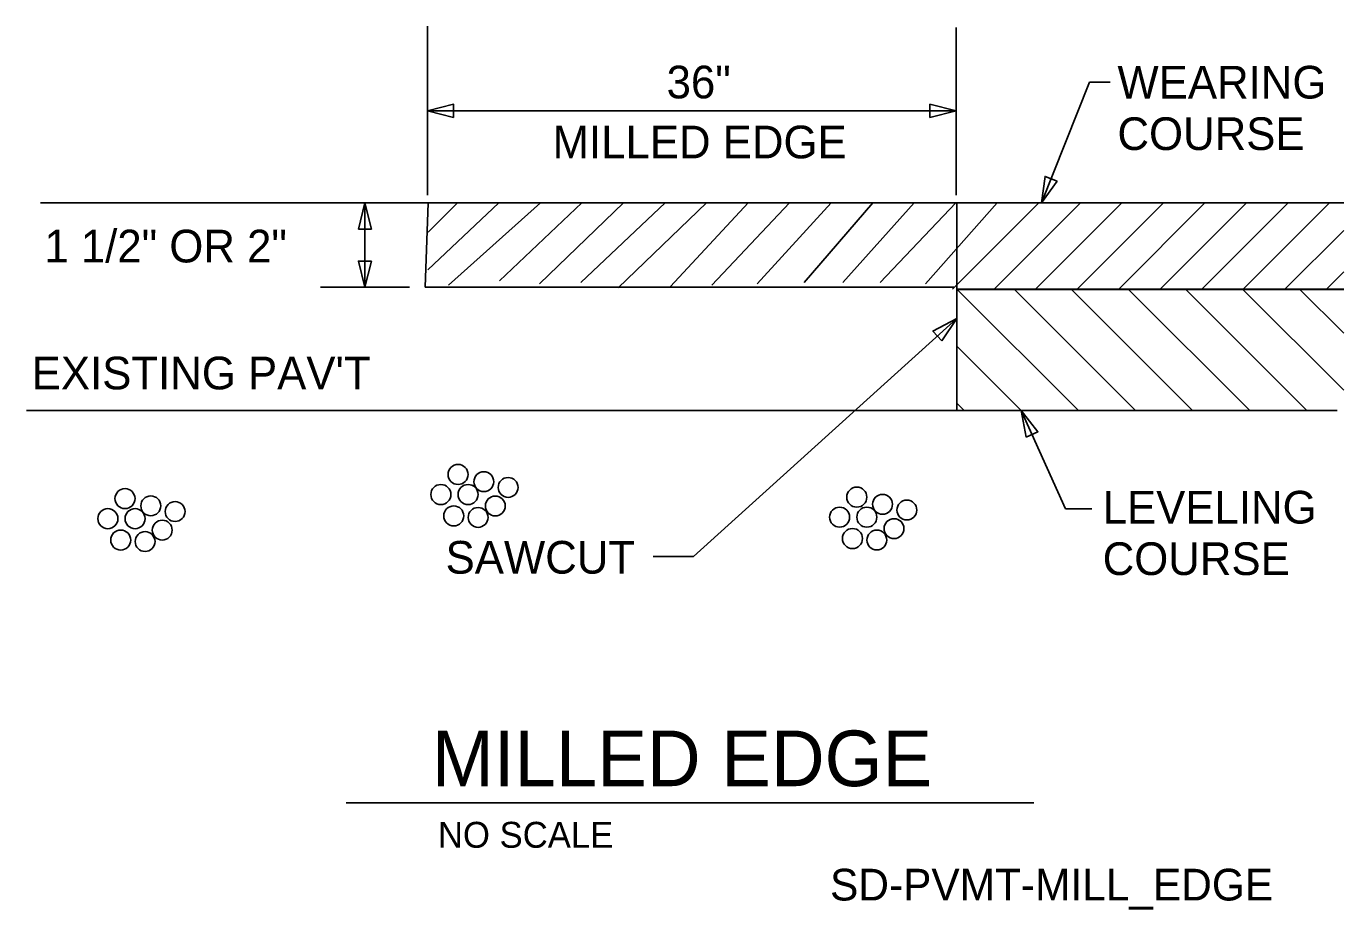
# Model space of a CAD drawing. Extents: x 10126.6 to 10168.6, y 10025.9 to 10054.1.
import ezdxf

# ---------------------------------------------------------------- set-up
doc = ezdxf.new("R2010")
doc.units = 0
for name, color, linetype in [('Default', 7, 'Continuous'), ('G-ANNO-TEXT', 7, 'Continuous'), ('G-ANNO-TTXT', 7, 'Continuous'), ('G-DETL-LINE', 7, 'Continuous'), ('G-DETL-PATT', 7, 'Continuous')]:
    doc.layers.add(name, color=color, linetype=linetype)

msp = doc.modelspace()

# ---------------------------------------------------------------- linework, layer by layer
at = {"layer": 'Default'}
for p, q in [((10139.407, 10048.484), (10139.319, 10045.8)), ((10156.278, 10045.72), (10168.633, 10045.72)), ((10156.28, 10045.73), (10156.28, 10041.854)), ((10156.52, 10041.854), (10156.28, 10042.094))]:
    msp.add_line(p, q, dxfattribs=at)
at = {"layer": 'G-ANNO-TEXT'}
for p, q in [((10139.389, 10048.73), (10139.389, 10054.126)), ((10156.26, 10048.73), (10156.26, 10054.085)), ((10160.523, 10052.343), (10161.184, 10052.343)), ((10139.389, 10051.428), (10156.26, 10051.428)), ((10137.392, 10045.795), (10137.392, 10048.484)), ((10156.28, 10048.484), (10156.28, 10045.73)), ((10138.812, 10045.795), (10135.973, 10045.795)), ((10136.796, 10029.328), (10158.746, 10029.328))]:
    msp.add_line(p, q, dxfattribs=at)
for points in [[(10140.222, 10051.219), (10139.389, 10051.428), (10140.222, 10051.636)], [(10155.427, 10051.636), (10156.26, 10051.428), (10155.427, 10051.219)], [(10137.184, 10047.651), (10137.392, 10048.484), (10137.601, 10047.651)], [(10137.601, 10046.629), (10137.392, 10045.795), (10137.184, 10046.629)], [(10155.802, 10044.084), (10156.28, 10044.798), (10155.522, 10044.393)]]:
    msp.add_lwpolyline(points, close=True, dxfattribs=at)
msp.add_lwpolyline([(10156.28, 10044.798), (10147.878, 10037.197), (10146.587, 10037.197)], dxfattribs=at)
at = {"layer": 'G-ANNO-TTXT'}
msp.add_line((10158.987, 10048.484), (10160.523, 10052.343), dxfattribs=at)
for points in [[(10159.489, 10049.181), (10158.987, 10048.484), (10159.102, 10049.335)], [(10159.489, 10049.181), (10158.987, 10048.484), (10159.102, 10049.335)], [(10158.496, 10041.008), (10158.343, 10041.854), (10158.876, 10041.18)]]:
    msp.add_lwpolyline(points, close=True, dxfattribs=at)
msp.add_lwpolyline([(10158.343, 10041.854), (10159.758, 10038.718), (10160.594, 10038.718)], dxfattribs=at)
at = {"layer": 'G-DETL-LINE'}
for p, q in [((10127.039, 10048.484), (10139.407, 10048.484)), ((10139.407, 10048.484), (10168.633, 10048.484)), ((10139.319, 10045.8), (10156.19, 10045.8)), ((10156.278, 10045.73), (10168.633, 10045.73)), ((10126.584, 10041.854), (10168.429, 10041.854))]:
    msp.add_line(p, q, dxfattribs=at)
at = {"layer": 'G-DETL-PATT'}
for p, q in [((10139.395, 10046.346), (10141.666, 10048.484)), ((10139.407, 10047.551), (10140.341, 10048.484)), ((10140.056, 10045.861), (10142.992, 10048.484)), ((10141.685, 10045.993), (10144.318, 10048.484)), ((10142.961, 10045.905), (10145.644, 10048.484)), ((10144.282, 10045.949), (10146.97, 10048.484)), ((10145.471, 10045.773), (10148.295, 10048.484)), ((10147.144, 10045.817), (10149.621, 10048.484)), ((10148.464, 10045.861), (10150.947, 10048.484)), ((10149.917, 10045.905), (10152.273, 10048.484)), ((10151.414, 10045.949), (10153.599, 10048.484)), ((10152.647, 10045.949), (10154.925, 10048.484)), ((10153.835, 10045.949), (10156.25, 10048.484)), ((10155.288, 10045.905), (10157.576, 10048.484)), ((10156.148, 10045.73), (10158.902, 10048.484)), ((10157.473, 10045.73), (10160.228, 10048.484)), ((10158.799, 10045.73), (10161.554, 10048.484)), ((10160.125, 10045.73), (10162.88, 10048.484)), ((10161.451, 10045.73), (10164.205, 10048.484)), ((10162.777, 10045.73), (10165.531, 10048.484)), ((10164.102, 10045.73), (10166.857, 10048.484)), ((10165.428, 10045.73), (10168.183, 10048.484)), ((10166.754, 10045.73), (10168.633, 10047.608)), ((10168.08, 10045.73), (10168.633, 10046.282)), ((10160.166, 10041.854), (10156.29, 10045.73)), ((10161.989, 10041.854), (10158.113, 10045.73)), ((10163.812, 10041.854), (10159.936, 10045.73)), ((10165.635, 10041.854), (10161.759, 10045.73)), ((10167.458, 10041.854), (10163.582, 10045.73)), ((10168.633, 10042.502), (10165.405, 10045.73)), ((10168.633, 10044.325), (10167.228, 10045.73)), ((10158.343, 10041.854), (10156.28, 10043.917))]:
    msp.add_line(p, q, dxfattribs=at)
for centre, radius in [((10140.364, 10039.814), 0.32), ((10141.187, 10039.584), 0.317), ((10141.962, 10039.401), 0.317), ((10129.733, 10039.043), 0.32), ((10139.816, 10039.173), 0.32), ((10140.684, 10039.173), 0.32), ((10153.091, 10039.091), 0.32), ((10153.914, 10038.861), 0.317), ((10130.556, 10038.813), 0.317), ((10131.332, 10038.63), 0.317), ((10140.226, 10038.491), 0.32), ((10141.004, 10038.443), 0.317), ((10141.552, 10038.808), 0.317), ((10152.544, 10038.451), 0.32), ((10153.412, 10038.451), 0.32), ((10154.69, 10038.678), 0.317), ((10129.186, 10038.403), 0.32), ((10130.054, 10038.403), 0.32), ((10130.922, 10038.037), 0.317), ((10154.28, 10038.085), 0.317), ((10129.596, 10037.72), 0.32), ((10130.374, 10037.672), 0.317), ((10152.954, 10037.768), 0.32), ((10153.732, 10037.72), 0.317)]:
    msp.add_circle(centre, radius, dxfattribs=at)

# ---------------------------------------------------------------- texts
at = {"layer": 'G-ANNO-TEXT'}
for s, height, p in [('36"', 1.044, (10147.021, 10051.825)), ('WEARING ', 1.044, (10161.412, 10051.82)), ('MILLED EDGE', 1.044, (10143.382, 10049.91)), ('COURSE', 1.044, (10161.412, 10050.176)), ("EXISTING PAV'T", 1.044, (10126.755, 10042.532)), ('LEVELING ', 1.044, (10160.94, 10038.247)), ('SAWCUT', 1.044, (10139.966, 10036.647)), ('COURSE', 1.044, (10160.94, 10036.603)), ('MILLED EDGE ', 1.776, (10139.527, 10029.86)), ('NO SCALE', 0.828, (10139.721, 10027.893)), ('SD-PVMT-MILL_EDGE', 1.0125, (10152.238, 10026.209))]:
    msp.add_text(s, height=height, dxfattribs=at).set_placement(p)
msp.add_text('1 1/2" OR 2"', height=1.044, rotation=360, dxfattribs=at).set_placement((10127.159, 10046.586))

doc.saveas('drawing.dxf')
